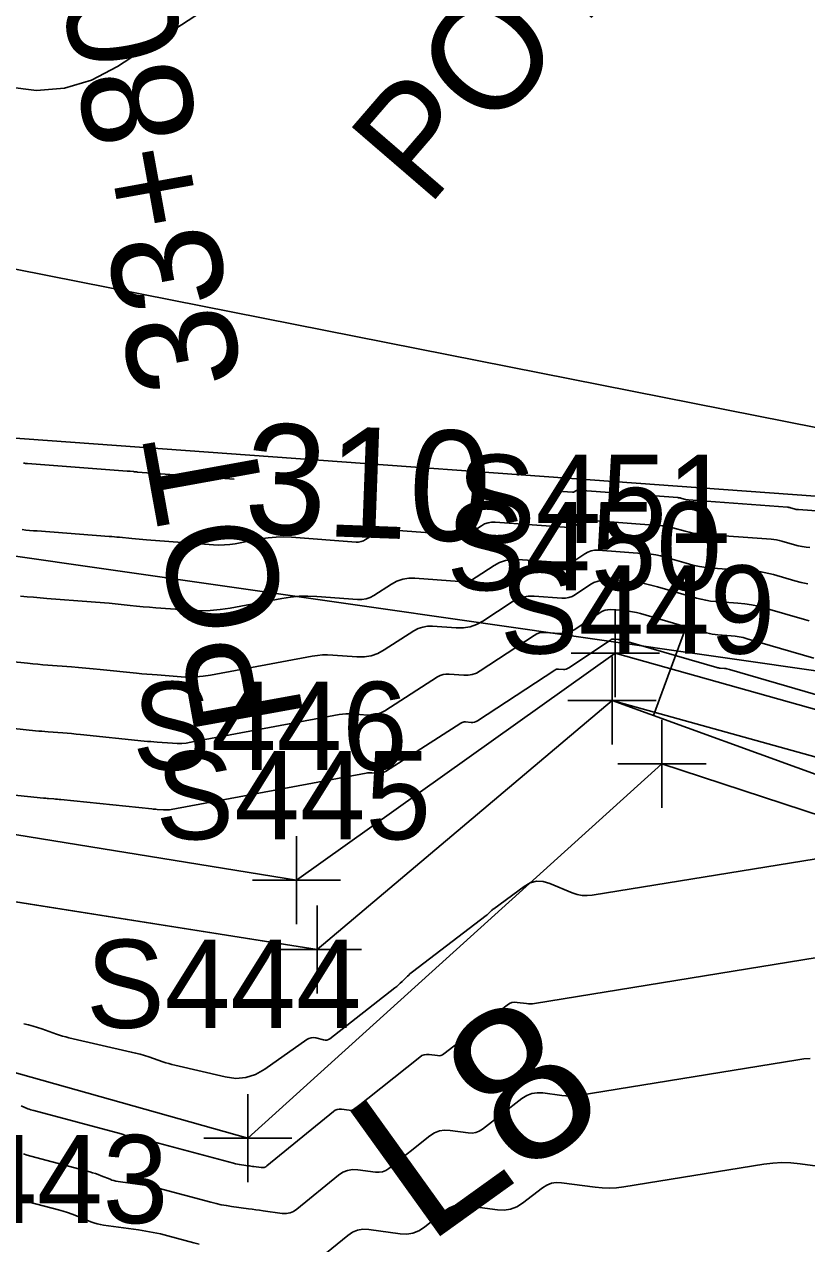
# Model space of a CAD drawing. Extents: x 816928 to 825690, y 436959 to 448212.
# Drawn here: x 819046 to 819081.5, y 445108.4 to 445163.8 of the extents above; entities that cross this region are included whole.
import ezdxf

# ---------------------------------------------------------------- set-up
doc = ezdxf.new("R2010")
doc.units = 0
for name, color, linetype in [('SURVEY - CONTOURS - Index with Text', 7, 'Continuous'), ('SURVEY - CONTOURS - Intermediate with optional Text', 7, 'Continuous'), ('SURVEY - DRAINAGE - Bridge Hydraulic Data - Points - Locators', 7, 'Continuous'), ('SURVEY - DRAINAGE - Bridge Hydraulic Data - Points - Numbers', 7, 'Continuous'), ('SURVEY - DRAINAGE - Bridge Hydraulic Data with Text', 7, 'Continuous'), ('SURVEY - DRAINAGE - Natural Features', 7, 'Continuous'), ('SURVEY - DRAINAGE - Natural Features - Points - Locators', 7, 'Continuous'), ('SURVEY - DRAINAGE - Natural Features - Points - Numbers', 7, 'Continuous'), ('SURVEY - NON-TRANSPORTATION - Features', 7, 'Continuous'), ('SURVEY - PROPERTY - Parcels', 7, 'Continuous'), ('SURVEY - PROPERTY - Property Lines', 7, 'Continuous')]:
    doc.layers.add(name, color=color, linetype=linetype)

msp = doc.modelspace()

# ---------------------------------------------------------------- linework, layer by layer
at = {"layer": 'SURVEY - CONTOURS - Index with Text'}
for points in [[(819045.245, 445160.912), (819046.566, 445160.756), (819047.837, 445160.859), (819049.061, 445161.222), (819050.236, 445161.845), (819055.041, 445164.988)], [(819055.528, 445143.118), (819051.139, 445143.447), (819051.093, 445143.451), (819051.047, 445143.455), (819051.002, 445143.459), (819050.956, 445143.464), (819050.806, 445143.479), (819050.774, 445143.482), (819050.742, 445143.485), (819050.71, 445143.488), (819050.678, 445143.49), (819046.156, 445143.83), (819046.11, 445143.833), (819046.064, 445143.837), (819046.018, 445143.841), (819045.972, 445143.846)], [(819085.58, 445141.41), (819081.111, 445141.74), (819081.06, 445141.745), (819081.009, 445141.753), (819080.96, 445141.763), (819080.91, 445141.776), (819080.75, 445141.823), (819080.715, 445141.832), (819080.68, 445141.839), (819080.645, 445141.845), (819080.609, 445141.848), (819076.132, 445142.178), (819076.082, 445142.183), (819076.033, 445142.191), (819075.983, 445142.201), (819075.935, 445142.214), (819075.777, 445142.26), (819075.743, 445142.269), (819075.708, 445142.276), (819075.673, 445142.281), (819075.638, 445142.285), (819071.108, 445142.618), (819071.082, 445142.618), (819071.057, 445142.614), (819071.033, 445142.605), (819071.01, 445142.592), (819070.937, 445142.543), (819070.921, 445142.534), (819070.904, 445142.528), (819070.887, 445142.525), (819070.868, 445142.525), (819070.405, 445142.559)], [(819082.251, 445133.246), (819077.976, 445134.494), (819077.921, 445134.509), (819077.866, 445134.52), (819077.81, 445134.529), (819077.753, 445134.534), (819077.567, 445134.548), (819077.528, 445134.552), (819077.489, 445134.558), (819077.45, 445134.566), (819077.411, 445134.576), (819073.173, 445135.809), (819073.115, 445135.824), (819073.055, 445135.836), (819072.996, 445135.845), (819072.935, 445135.851), (819072.737, 445135.866), (819072.696, 445135.866), (819072.656, 445135.859), (819072.618, 445135.845), (819072.582, 445135.825), (819070.702, 445134.56), (819070.645, 445134.528), (819070.584, 445134.506), (819070.521, 445134.495), (819070.455, 445134.495), (819070.235, 445134.511), (819070.189, 445134.511), (819070.145, 445134.503), (819070.103, 445134.489), (819070.062, 445134.466), (819066.563, 445132.167), (819066.495, 445132.13), (819066.424, 445132.105), (819066.35, 445132.092), (819066.272, 445132.092), (819066.014, 445132.111), (819065.96, 445132.111), (819065.907, 445132.102), (819065.857, 445132.085), (819065.81, 445132.059), (819062.395, 445129.867), (819062.317, 445129.825), (819062.235, 445129.797), (819062.15, 445129.782), (819062.062, 445129.782), (819061.766, 445129.804), (819061.703, 445129.807), (819061.64, 445129.805), (819061.577, 445129.8), (819061.515, 445129.79), (819052.678, 445128.143), (819052.591, 445128.13), (819052.503, 445128.122), (819052.416, 445128.12), (819052.328, 445128.124), (819052.039, 445128.146), (819051.977, 445128.15), (819051.916, 445128.156), (819051.854, 445128.161), (819051.792, 445128.168), (819047.666, 445128.59), (819047.588, 445128.598), (819047.511, 445128.605), (819047.433, 445128.612), (819047.356, 445128.618), (819047.102, 445128.637), (819047.047, 445128.641), (819046.993, 445128.646), (819046.939, 445128.651), (819046.885, 445128.656), (819042.651, 445129.092)], [(819045.996, 445118.418), (819046.202, 445118.368), (819046.407, 445118.312), (819046.61, 445118.251), (819046.811, 445118.183), (819047.466, 445117.954), (819047.607, 445117.907), (819047.749, 445117.863), (819047.893, 445117.824), (819048.037, 445117.789), (819050.861, 445117.137), (819051.061, 445117.088), (819051.26, 445117.035), (819051.457, 445116.976), (819051.652, 445116.913), (819052.289, 445116.697), (819052.426, 445116.653), (819052.564, 445116.612), (819052.703, 445116.574), (819052.843, 445116.54), (819055.121, 445116.008), (819055.599, 445115.944), (819056.058, 445115.981), (819056.497, 445116.119), (819056.916, 445116.358), (819058.819, 445117.703), (819058.914, 445117.756), (819059.013, 445117.787), (819059.116, 445117.794), (819059.224, 445117.778), (819059.583, 445117.686), (819059.659, 445117.675), (819059.73, 445117.681), (819059.798, 445117.704), (819059.863, 445117.744), (819062.815, 445120.05), (819062.898, 445120.117), (819062.979, 445120.187), (819063.059, 445120.259), (819063.136, 445120.333), (819063.384, 445120.58), (819063.438, 445120.632), (819063.494, 445120.682), (819063.551, 445120.73), (819063.61, 445120.777), (819066.954, 445123.326), (819066.99, 445123.354), (819067.025, 445123.384), (819067.058, 445123.415), (819067.091, 445123.447), (819067.196, 445123.554), (819067.219, 445123.577), (819067.242, 445123.598), (819067.267, 445123.619), (819067.292, 445123.638), (819068.668, 445124.648), (819068.946, 445124.807), (819069.233, 445124.883), (819069.531, 445124.877), (819069.838, 445124.787), (819070.858, 445124.361), (819071.078, 445124.286), (819071.302, 445124.243), (819071.53, 445124.233), (819071.762, 445124.255), (819084.155, 445126.266)]]:
    msp.add_lwpolyline(points, dxfattribs=at)
at = {"layer": 'SURVEY - CONTOURS - Intermediate with optional Text'}
for points in [[(819081.631, 445140.016), (819081.452, 445140.034), (819081.275, 445140.062), (819081.099, 445140.098), (819080.925, 445140.144), (819080.36, 445140.309), (819080.238, 445140.341), (819080.116, 445140.367), (819079.992, 445140.386), (819079.866, 445140.398), (819076.68, 445140.633), (819076.502, 445140.651), (819076.326, 445140.678), (819076.152, 445140.714), (819075.98, 445140.759), (819075.419, 445140.922), (819075.298, 445140.954), (819075.176, 445140.979), (819075.053, 445140.998), (819074.929, 445141.011), (819071.566, 445141.258), (819071.472, 445141.258), (819071.382, 445141.242), (819071.296, 445141.211), (819071.215, 445141.165), (819070.954, 445140.99), (819070.897, 445140.958), (819070.837, 445140.936), (819070.774, 445140.925), (819070.709, 445140.925), (819067.364, 445141.172), (819067.197, 445141.171), (819067.037, 445141.143), (819066.883, 445141.089), (819066.737, 445141.009), (819066.269, 445140.701), (819066.166, 445140.645), (819066.059, 445140.607), (819065.947, 445140.588), (819065.83, 445140.588), (819062.56, 445140.83), (819062.396, 445140.83), (819062.239, 445140.804), (819062.088, 445140.752), (819061.944, 445140.674), (819061.484, 445140.379), (819061.383, 445140.324), (819061.277, 445140.288), (819061.167, 445140.27), (819061.053, 445140.27), (819058.133, 445140.488), (819057.778, 445140.503), (819057.424, 445140.495), (819057.071, 445140.464), (819056.72, 445140.41), (819055.574, 445140.196), (819055.328, 445140.159), (819055.081, 445140.137), (819054.833, 445140.131), (819054.584, 445140.142), (819051.559, 445140.369), (819051.39, 445140.382), (819051.221, 445140.397), (819051.052, 445140.412), (819050.883, 445140.429), (819050.332, 445140.485), (819050.214, 445140.497), (819050.096, 445140.508), (819049.977, 445140.518), (819049.859, 445140.527), (819046.593, 445140.772), (819046.422, 445140.786), (819046.25, 445140.801), (819046.079, 445140.816), (819045.908, 445140.833)], [(819081.54, 445138.37), (819081.238, 445138.433), (819080.94, 445138.512), (819079.971, 445138.795), (819079.762, 445138.85), (819079.551, 445138.894), (819079.338, 445138.927), (819079.123, 445138.948), (819077.227, 445139.088), (819076.922, 445139.118), (819076.62, 445139.165), (819076.321, 445139.227), (819076.024, 445139.305), (819075.061, 445139.585), (819074.853, 445139.639), (819074.644, 445139.683), (819074.432, 445139.715), (819074.219, 445139.736), (819072.023, 445139.898), (819071.862, 445139.897), (819071.707, 445139.87), (819071.56, 445139.817), (819071.419, 445139.738), (819070.971, 445139.436), (819070.873, 445139.381), (819070.77, 445139.344), (819070.662, 445139.325), (819070.549, 445139.324), (819068.391, 445139.484), (819068.103, 445139.482), (819067.826, 445139.435), (819067.562, 445139.342), (819067.309, 445139.203), (819066.504, 445138.674), (819066.327, 445138.577), (819066.142, 445138.512), (819065.949, 445138.479), (819065.747, 445138.478), (819063.721, 445138.628), (819063.439, 445138.628), (819063.168, 445138.582), (819062.908, 445138.493), (819062.659, 445138.359), (819061.866, 445137.85), (819061.692, 445137.756), (819061.51, 445137.693), (819061.32, 445137.662), (819061.122, 445137.661), (819059.27, 445137.8), (819058.873, 445137.816), (819058.479, 445137.808), (819058.085, 445137.773), (819057.693, 445137.713), (819055.338, 445137.274), (819054.887, 445137.205), (819054.435, 445137.165), (819053.981, 445137.155), (819053.525, 445137.175), (819051.98, 445137.291), (819051.687, 445137.314), (819051.395, 445137.338), (819051.103, 445137.365), (819050.811, 445137.394), (819049.858, 445137.492), (819049.654, 445137.512), (819049.449, 445137.531), (819049.245, 445137.549), (819049.04, 445137.565), (819047.03, 445137.715), (819046.733, 445137.739), (819046.436, 445137.764), (819046.14, 445137.791), (819045.843, 445137.821)], [(819081.588, 445136.701), (819081.378, 445136.756), (819079.595, 445137.277), (819079.292, 445137.357), (819078.986, 445137.42), (819078.678, 445137.468), (819078.366, 445137.499), (819077.344, 445137.574), (819077.126, 445137.596), (819076.91, 445137.629), (819076.695, 445137.674), (819076.483, 445137.729), (819074.725, 445138.241), (819074.42, 445138.321), (819074.112, 445138.385), (819073.8, 445138.433), (819073.486, 445138.464), (819072.455, 445138.54), (819072.239, 445138.539), (819072.032, 445138.502), (819071.834, 445138.431), (819071.646, 445138.325), (819070.995, 445137.887), (819070.852, 445137.807), (819070.702, 445137.753), (819070.545, 445137.726), (819070.381, 445137.725), (819069.122, 445137.818), (819068.857, 445137.817), (819068.604, 445137.773), (819068.361, 445137.688), (819068.13, 445137.56), (819066.799, 445136.686), (819066.518, 445136.531), (819066.223, 445136.427), (819065.915, 445136.375), (819065.594, 445136.373), (819064.523, 445136.453), (819064.298, 445136.452), (819064.082, 445136.416), (819063.875, 445136.345), (819063.677, 445136.238), (819062.33, 445135.374), (819062.041, 445135.218), (819061.738, 445135.114), (819061.423, 445135.061), (819061.094, 445135.06), (819059.999, 445135.142), (819059.765, 445135.152), (819059.532, 445135.147), (819059.299, 445135.126), (819059.068, 445135.091), (819054.451, 445134.23), (819054.122, 445134.18), (819053.791, 445134.151), (819053.459, 445134.144), (819053.126, 445134.158), (819052.036, 445134.24), (819051.802, 445134.258), (819051.569, 445134.278), (819051.335, 445134.299), (819051.102, 445134.322), (819049.456, 445134.491), (819049.13, 445134.523), (819048.803, 445134.554), (819048.476, 445134.581), (819048.149, 445134.607), (819047.08, 445134.687), (819046.851, 445134.705), (819046.622, 445134.725), (819046.393, 445134.746), (819046.164, 445134.769), (819044.453, 445134.945)], [(819081.814, 445135.001), (819078.786, 445135.886), (819078.607, 445135.933), (819078.426, 445135.97), (819078.244, 445135.998), (819078.06, 445136.017), (819077.456, 445136.061), (819077.327, 445136.074), (819077.199, 445136.094), (819077.073, 445136.12), (819076.947, 445136.153), (819073.949, 445137.025), (819073.767, 445137.072), (819073.583, 445137.111), (819073.398, 445137.139), (819073.211, 445137.158), (819072.596, 445137.203), (819072.467, 445137.202), (819072.344, 445137.181), (819072.226, 445137.138), (819072.114, 445137.075), (819070.976, 445136.309), (819070.81, 445136.216), (819070.637, 445136.154), (819070.455, 445136.122), (819070.266, 445136.121), (819069.633, 445136.168), (819069.5, 445136.167), (819069.373, 445136.145), (819069.251, 445136.103), (819069.134, 445136.038), (819066.681, 445134.426), (819066.506, 445134.33), (819066.323, 445134.266), (819066.132, 445134.233), (819065.933, 445134.233), (819065.269, 445134.282), (819065.129, 445134.281), (819064.995, 445134.259), (819064.866, 445134.215), (819064.743, 445134.149), (819062.363, 445132.62), (819062.179, 445132.521), (819061.987, 445132.455), (819061.787, 445132.422), (819061.578, 445132.421), (819060.883, 445132.473), (819060.734, 445132.479), (819060.586, 445132.476), (819060.438, 445132.463), (819060.291, 445132.441), (819053.565, 445131.187), (819053.356, 445131.155), (819053.147, 445131.137), (819052.937, 445131.132), (819052.727, 445131.141), (819052.037, 445131.193), (819051.89, 445131.204), (819051.742, 445131.217), (819051.595, 445131.23), (819051.447, 445131.245), (819048.561, 445131.541), (819048.359, 445131.561), (819048.157, 445131.579), (819047.955, 445131.597), (819047.752, 445131.613), (819047.091, 445131.662), (819046.949, 445131.673), (819046.807, 445131.685), (819046.666, 445131.698), (819046.525, 445131.712), (819043.552, 445132.018)], [(819045.865, 445114.694), (819046.173, 445114.569), (819046.239, 445114.544), (819046.306, 445114.52), (819046.374, 445114.499), (819046.442, 445114.479), (819050.397, 445113.422), (819050.449, 445113.407), (819050.501, 445113.391), (819050.552, 445113.373), (819050.602, 445113.353), (819050.767, 445113.287), (819050.802, 445113.274), (819050.839, 445113.263), (819050.875, 445113.254), (819050.913, 445113.248), (819051.309, 445113.193), (819051.394, 445113.18), (819051.478, 445113.164), (819051.562, 445113.146), (819051.645, 445113.125), (819055.493, 445112.095), (819055.583, 445112.073), (819055.673, 445112.053), (819055.765, 445112.036), (819055.857, 445112.022), (819056.158, 445111.98), (819056.222, 445111.971), (819056.287, 445111.962), (819056.351, 445111.953), (819056.416, 445111.945), (819056.755, 445111.898), (819056.826, 445111.895), (819056.893, 445111.906), (819056.955, 445111.931), (819057.014, 445111.971), (819060.024, 445114.438), (819060.109, 445114.495), (819060.199, 445114.531), (819060.295, 445114.548), (819060.396, 445114.543), (819060.738, 445114.496), (819060.809, 445114.493), (819060.876, 445114.504), (819060.94, 445114.529), (819061, 445114.568), (819063.943, 445116.912), (819064.038, 445116.974), (819064.14, 445117.013), (819064.247, 445117.031), (819064.36, 445117.026), (819064.741, 445116.974), (819064.82, 445116.971), (819064.896, 445116.983), (819064.967, 445117.01), (819065.034, 445117.052), (819067.9, 445119.269), (819068.005, 445119.336), (819068.117, 445119.379), (819068.236, 445119.398), (819068.36, 445119.392), (819068.779, 445119.335), (819068.868, 445119.326), (819068.958, 445119.324), (819069.047, 445119.329), (819069.136, 445119.34), (819082.614, 445121.527)], [(819045.975, 445112.515), (819046.138, 445112.463), (819046.304, 445112.416), (819048.979, 445111.701), (819049.109, 445111.664), (819049.237, 445111.623), (819049.364, 445111.579), (819049.49, 445111.53), (819049.898, 445111.365), (819049.987, 445111.332), (819050.077, 445111.305), (819050.168, 445111.284), (819050.261, 445111.268), (819051.246, 445111.133), (819051.457, 445111.1), (819051.666, 445111.061), (819051.874, 445111.016), (819052.08, 445110.964), (819054.475, 445110.323), (819054.706, 445110.265), (819054.938, 445110.214), (819055.172, 445110.171), (819055.407, 445110.135), (819056.178, 445110.029), (819056.343, 445110.006), (819056.508, 445109.983), (819056.673, 445109.96), (819056.838, 445109.938), (819057.707, 445109.818), (819057.888, 445109.81), (819058.058, 445109.839), (819058.219, 445109.904), (819058.369, 445110.005), (819060.257, 445111.553), (819060.456, 445111.686), (819060.667, 445111.771), (819060.892, 445111.809), (819061.131, 445111.799), (819061.932, 445111.689), (819062.099, 445111.682), (819062.257, 445111.708), (819062.406, 445111.766), (819062.546, 445111.858), (819064.401, 445113.335), (819064.609, 445113.47), (819064.83, 445113.557), (819065.064, 445113.595), (819065.312, 445113.585), (819066.143, 445113.471), (819066.316, 445113.464), (819066.481, 445113.49), (819066.637, 445113.549), (819066.783, 445113.642), (819068.574, 445115.028), (819068.791, 445115.165), (819069.021, 445115.253), (819069.264, 445115.292), (819069.521, 445115.281), (819070.381, 445115.164), (819070.565, 445115.145), (819070.749, 445115.141), (819070.933, 445115.15), (819071.117, 445115.173), (819081.074, 445116.789), (819081.355, 445116.824), (819081.637, 445116.838)], [(819059.707, 445108.025), (819060.677, 445108.82), (819060.893, 445108.965), (819061.122, 445109.058), (819061.367, 445109.099), (819061.626, 445109.088), (819063.054, 445108.892), (819063.352, 445108.879), (819063.633, 445108.925), (819063.899, 445109.03), (819064.149, 445109.193), (819065.08, 445109.934), (819065.286, 445110.068), (819065.505, 445110.155), (819065.738, 445110.192), (819065.984, 445110.182), (819067.461, 445109.98), (819067.77, 445109.966), (819068.062, 445110.013), (819068.339, 445110.119), (819068.6, 445110.284), (819069.499, 445110.98), (819069.698, 445111.106), (819069.909, 445111.187), (819070.132, 445111.222), (819070.367, 445111.212), (819071.889, 445111.005), (819072.215, 445110.972), (819072.541, 445110.964), (819072.866, 445110.981), (819073.191, 445111.021), (819079.533, 445112.051), (819079.944, 445112.102), (819080.356, 445112.123), (819080.768, 445112.113), (819081.18, 445112.072), (819082.528, 445111.889)], [(819045.939, 445110.418), (819046.236, 445110.334), (819047.562, 445109.98), (819047.769, 445109.921), (819047.974, 445109.856), (819048.177, 445109.784), (819048.377, 445109.707), (819049.03, 445109.443), (819049.171, 445109.391), (819049.315, 445109.348), (819049.46, 445109.314), (819049.609, 445109.289), (819051.183, 445109.072), (819051.519, 445109.02), (819051.854, 445108.958), (819052.186, 445108.886), (819052.516, 445108.803), (819053.693, 445108.488), (819053.946, 445108.424)]]:
    msp.add_lwpolyline(points, dxfattribs=at)
at = {"layer": 'SURVEY - DRAINAGE - Bridge Hydraulic Data - Points - Locators'}
for p, q in [((819072.804, 445137.23), (819072.804, 445133.23)), ((819074.804, 445135.23), (819070.804, 445135.23)), ((819074.922, 445132.209), (819074.922, 445128.209)), ((819076.922, 445130.209), (819072.922, 445130.209)), ((819058.351, 445126.932), (819058.351, 445122.932)), ((819060.351, 445124.932), (819056.351, 445124.932)), ((819056.145, 445115.232), (819056.145, 445111.232)), ((819058.145, 445113.232), (819054.145, 445113.232))]:
    msp.add_line(p, q, dxfattribs=at)
at = {"layer": 'SURVEY - DRAINAGE - Bridge Hydraulic Data with Text'}
for p, q in [((819074.545, 445132.396), (819076.254, 445137.095)), ((819059.296, 445121.786), (819072.661, 445133.081)), ((819072.661, 445133.081), (819153.488, 445103.692)), ((819026.376, 445126.987), (819059.296, 445121.786))]:
    msp.add_line(p, q, dxfattribs=at)
for points in [[(818981.856, 445170.386), (819027.381, 445129.952), (819058.351, 445124.932), (819072.804, 445135.23), (819108.826, 445125.102), (819154.553, 445106.813)], [(818975.535, 445161.489), (819022.478, 445122.715), (819056.145, 445113.232), (819074.922, 445130.209), (819108.845, 445119.079), (819151.657, 445101.619)], [(819000.173, 445161.106), (819023.525, 445142.825), (819041.009, 445145.316), (819088.975, 445141.839), (819117.33, 445129.123), (819157.101, 445116.393)]]:
    msp.add_lwpolyline(points, dxfattribs=at)
at = {"layer": 'SURVEY - DRAINAGE - Natural Features'}
msp.add_lwpolyline([(818978.518, 445165.447), (819026.376, 445126.987), (819059.296, 445121.786), (819072.661, 445133.081), (819109.997, 445122.706), (819153.488, 445103.692)], dxfattribs=at)
at = {"layer": 'SURVEY - DRAINAGE - Natural Features - Points - Locators'}
for p, q in [((819072.661, 445135.081), (819072.661, 445131.081)), ((819074.661, 445133.081), (819070.661, 445133.081)), ((819059.296, 445123.786), (819059.296, 445119.786)), ((819061.296, 445121.786), (819057.296, 445121.786))]:
    msp.add_line(p, q, dxfattribs=at)
at = {"layer": 'SURVEY - NON-TRANSPORTATION - Features'}
msp.add_lwpolyline([(819158.05, 445117.872), (819088.932, 445144.076), (819035.901, 445154.568), (818997.299, 445172.969), (818992.372, 445174.875)], dxfattribs=at)
at = {"layer": 'SURVEY - PROPERTY - Parcels'}
for p, q in [((819369.901, 445093.159), (818979.924, 445149.041)), ((818979.924, 445149.041), (819369.901, 445093.159))]:
    msp.add_line(p, q, dxfattribs=at)
at = {"layer": 'SURVEY - PROPERTY - Property Lines'}
msp.add_line((818979.924, 445149.041), (819369.901, 445093.159), dxfattribs=at)

# ---------------------------------------------------------------- texts
at = {"layer": 'SURVEY - CONTOURS - Index with Text'}
msp.add_text('310', height=5, rotation=357.8484, dxfattribs=at).set_placement((819055.93, 445140.679))
at = {"layer": 'SURVEY - DRAINAGE - Bridge Hydraulic Data - Points - Numbers'}
for s, p in [('S451', (819065.626, 445140.23)), ('S449', (819067.57, 445135.209)), ('S446', (819050.904, 445129.932)), ('S444', (819048.809, 445118.232)), ('S443', (819040.047, 445109.376))]:
    msp.add_text(s, height=4, dxfattribs=at).set_placement(p)
at = {"layer": 'SURVEY - DRAINAGE - Bridge Hydraulic Data with Text'}
for s, height, rotation, p in [('POT 33+47.17', 5, 49.2373, (819064.293, 445155.408)), ('POT 33+80.50', 5, 100.253, (819058.72, 445132.218)), ('L8', 7, 35.6932, (819064.242, 445108.336))]:
    msp.add_text(s, height=height, rotation=rotation, dxfattribs=at).set_placement(p)
at = {"layer": 'SURVEY - DRAINAGE - Natural Features - Points - Numbers'}
for s, p in [('S450', (819065.152, 445138.081)), ('S445', (819051.96, 445126.786))]:
    msp.add_text(s, height=4, dxfattribs=at).set_placement(p)

doc.saveas('drawing.dxf')
